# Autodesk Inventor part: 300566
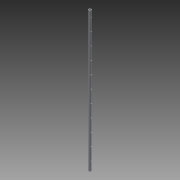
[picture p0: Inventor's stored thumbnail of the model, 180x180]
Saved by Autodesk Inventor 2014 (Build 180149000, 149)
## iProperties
Created: 2007-11
Part Number: 300566
Document SubType Name: Modeling
Designer: TH
Density: 2.71 g/cm^3
Mass: 9.33314 g
Surface Area: 70.624 cm^2
Volume: 3.44396 cm^3
Material: Aluminum-6061
Description: WIRE CONNECTOR BAR
Appearance: Aluminum - Flat
Component Category: Back Component
Author: TH
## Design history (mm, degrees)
sketch "Sketch1"
  geometry: C1 r 2.5 at (0, 0); C2 r 1.5 at (0, 0); 1 further point
  constraints: 2 centre point, 2 coincident
  dimensions: "d0" = 5 diameter of C1; "d1" = 3 diameter of C2
extrude "Extrusion1" new body sketch "Sketch1" stored distance "d2" = 280; taper "d3" = 0 deg
sketch "Sketch2"
  geometry: L1 (-1.5, 140)-(1.5, 140) reference; L2 (-2.5, 140)-(2.5, 140) reference; L3 (0, 140)-(0, 128); C1 r 1.025 at (0, 128); C2 r 1.025 at (0, 103); C3 r 1.025 at (0, 78); C4 r 1.025 at (0, 53); C5 r 1.025 at (0, 28); C6 r 1.025 at (0, 3); C7 r 1.025 at (0, -22); C8 r 1.025 at (0, -47); C9 r 1.025 at (0, -72); C10 r 1.025 at (0, -97); C11 r 1.025 at (0, -122); 1 further point
  constraints: 11 centre point, 2 end point, 1 coincident, 1 midpoint, 1 perpendicular, 1 vertical, 20 other
  dimensions: "d4" = 12 distance of L3.start L3.end; "d5" = 2.05 diameter of C1; "d8" = 25 distance of C1.centre C2.centre
extrude "Extrusion2" cut sketch "Sketch2" stored distance "d13" = 280; taper "d14" = 0 deg
body "Solid1"
node "Projected Loop1"
